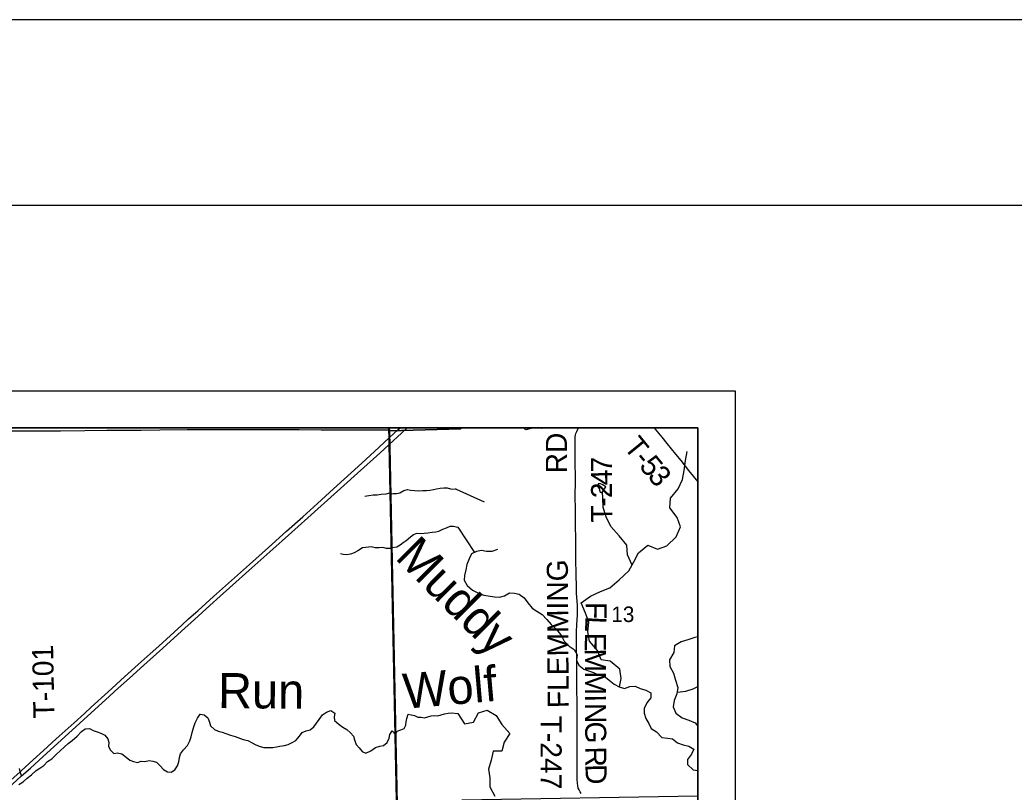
# Model space of a CAD drawing. Extents: x 0 to 34, y 0 to 22.
# Drawn here: x 7.072 to 9.752, y 19.918 to 22 of the extents above; entities that cross this region are included whole.
import ezdxf

# ---------------------------------------------------------------- set-up
doc = ezdxf.new("R2010")
doc.units = 0
for name, color, linetype in [('GM_X_County_Road', 7, 'Continuous'), ('GM_X_Interstate_Route', 7, 'Continuous'), ('GM_X_Major_River', 7, 'Continuous'), ('GM_X_Minor_Lake', 7, 'Continuous'), ('GM_X_Minor_River', 7, 'Continuous'), ('GM_X_Minor_River_Text', 7, 'Continuous'), ('GM_X_Section_Text', 7, 'Continuous'), ('GM_X_State_Shield', 7, 'Continuous'), ('GM_X_Township_Road', 7, 'Continuous'), ('GM_X_Township_Road_Text', 7, 'Continuous'), ('GM_X_US_Route', 7, 'Continuous'), ('SH_Border', 7, 'Continuous'), ('SH_Cut_Line', 7, 'Continuous'), ('SH_Data', 7, 'Continuous')]:
    doc.layers.add(name, color=color, linetype=linetype)

msp = doc.modelspace()

# ---------------------------------------------------------------- linework, layer by layer
at = {"layer": 'GM_X_County_Road'}
msp.add_lwpolyline([(7.0499, 20.8923), (7.0577, 20.8923), (7.0888, 20.8923), (7.1447, 20.8923), (7.182, 20.8924), (7.2473, 20.8928), (7.3063, 20.8935), (7.3684, 20.8939), (7.3995, 20.894), (7.4492, 20.8947), (7.5237, 20.8952), (7.5517, 20.8954), (7.5734, 20.8957), (7.62, 20.8958), (7.6604, 20.8959), (7.7132, 20.8958), (7.7443, 20.8958), (7.825, 20.8954), (7.884, 20.8951), (7.9337, 20.895), (7.9959, 20.8949), (8.0672, 20.8949)], dxfattribs=at)
at = {"layer": 'GM_X_Interstate_Route'}
for points in [[(8.1285, 16.8707), (8.1148, 17.8694), (8.0976, 18.2853), (8.0958, 18.3144), (8.0817, 18.88), (8.0959, 19.2713), (8.1023, 19.3817), (8.0929, 19.6339), (8.0678, 20.8562), (8.0675, 20.8733), (8.067, 20.8954), (8.0669, 20.9), (3.0331, 20.9), (3.0588, 19.9042), (3.067, 19.3838), (3.0747, 18.8969), (3.0724, 18.2926), (3.0939, 16.8719)], [(8.9, 16.8746), (8.9, 20.9), (8.0669, 20.9), (8.067, 20.8954), (8.0675, 20.8733), (8.0678, 20.8562), (8.0929, 19.6339), (8.1023, 19.3817), (8.0959, 19.2713), (8.0817, 18.88), (8.0958, 18.3144), (8.0976, 18.2853), (8.1148, 17.8694), (8.1285, 16.8707)]]:
    msp.add_lwpolyline(points, dxfattribs=at)
at = {"layer": 'GM_X_Major_River'}
for points in [[(8.4831, 20.9), (8.4784, 20.8982), (8.464, 20.8999), (8.4499, 20.8986), (8.4362, 20.895), (8.4319, 20.9)], [(8.3597, 20.572), (8.3447, 20.5664), (8.3303, 20.567), (8.317, 20.5691), (8.3029, 20.567), (8.2895, 20.5603), (8.2832, 20.5467), (8.2769, 20.5316), (8.274, 20.5168), (8.2708, 20.5024), (8.2702, 20.4891), (8.2784, 20.4749), (8.2927, 20.4626), (8.3085, 20.4547), (8.3225, 20.4492), (8.3514, 20.4443), (8.365, 20.4433), (8.3784, 20.4473), (8.3918, 20.4551), (8.4051, 20.4542), (8.4184, 20.4514), (8.4316, 20.4421), (8.4413, 20.4279), (8.4529, 20.4136), (8.4661, 20.4059), (8.48, 20.3969), (8.4931, 20.3834), (8.5043, 20.37), (8.5193, 20.3553), (8.5321, 20.3396), (8.5398, 20.325), (8.5526, 20.3115), (8.5661, 20.3026), (8.5743, 20.2884), (8.5726, 20.274), (8.5785, 20.2598), (8.592, 20.2498), (8.6052, 20.245), (8.6189, 20.2403), (8.6325, 20.2336), (8.6465, 20.2315), (8.6604, 20.2196), (8.674, 20.2091), (8.6875, 20.2017), (8.7023, 20.1977), (8.7165, 20.2028), (8.7309, 20.2034), (8.7445, 20.1975), (8.7597, 20.1931), (8.7729, 20.1857), (8.7731, 20.172), (8.7622, 20.1589), (8.7548, 20.1438), (8.7546, 20.1305), (8.7594, 20.1167), (8.7675, 20.1025), (8.7742, 20.0891), (8.7881, 20.0802), (8.8024, 20.0655), (8.8183, 20.0638), (8.8316, 20.0614), (8.8448, 20.0509), (8.8603, 20.045), (8.8754, 20.0414), (8.8886, 20.0336), (8.8827, 20.02), (8.8719, 20.0061), (8.8721, 19.9927), (8.8871, 19.9777), (8.9, 19.9758)]]:
    msp.add_lwpolyline(points, dxfattribs=at)
at = {"layer": 'GM_X_Minor_Lake'}
for points in [[(8.6517, 20.741), (8.6467, 20.7448), (8.6418, 20.7475), (8.6369, 20.7494), (8.6312, 20.749), (8.6304, 20.7414), (8.6334, 20.7361), (8.6346, 20.7319), (8.6368, 20.727), (8.6409, 20.7251)], [(8.0684, 20.7236), (8.0587, 20.7216), (8.0466, 20.7202), (8.0356, 20.7188), (8.0242, 20.7182), (8.0128, 20.7168), (8.0022, 20.715), (8.0022, 20.7146)], [(8.6409, 20.7251), (8.6517, 20.741)], [(8.0719, 20.5747), (8.0609, 20.5752), (8.051, 20.5772), (8.0412, 20.5765), (8.0298, 20.5766), (8.0189, 20.579), (8.0052, 20.5776), (7.9954, 20.5762), (7.9835, 20.5687), (7.9737, 20.5627), (7.9634, 20.5594), (7.9539, 20.5576), (7.9437, 20.5585), (7.9369, 20.5601)]]:
    msp.add_lwpolyline(points, dxfattribs=at)
at = {"layer": 'GM_X_Minor_River'}
for points in [[(8.6884, 20.2015), (8.6932, 20.2241), (8.6894, 20.2496), (8.6638, 20.2709), (8.6391, 20.2746), (8.6289, 20.2995), (8.6079, 20.3245), (8.6033, 20.35), (8.606, 20.3758), (8.5972, 20.4007), (8.5851, 20.4282), (8.6104, 20.4461), (8.6372, 20.4587), (8.6628, 20.4686), (8.6879, 20.4907), (8.7141, 20.5144), (8.7274, 20.5389), (8.7395, 20.5635), (8.7653, 20.5833), (8.791, 20.5734), (8.8159, 20.5818), (8.8409, 20.6062), (8.8527, 20.6331), (8.8436, 20.6587), (8.8242, 20.6848), (8.8261, 20.7103), (8.8466, 20.7355), (8.8587, 20.7608), (8.8625, 20.7855), (8.8663, 20.8116), (8.8709, 20.8367)], [(8.0715, 20.7216), (8.0786, 20.7232), (8.0873, 20.7228), (8.0964, 20.725), (8.1075, 20.7315), (8.117, 20.7334), (8.1254, 20.7318), (8.1356, 20.7314), (8.1478, 20.7299), (8.1585, 20.731), (8.168, 20.731), (8.1775, 20.7321), (8.187, 20.7336), (8.1957, 20.7355), (8.2056, 20.7378), (8.2148, 20.7381), (8.2239, 20.7385), (8.2326, 20.7358), (8.2479, 20.735), (8.2455, 20.735)], [(8.2479, 20.735), (8.324, 20.7003)], [(8.7226, 20.53), (8.7102, 20.5581), (8.7086, 20.5833), (8.6873, 20.6087), (8.6652, 20.6341), (8.6523, 20.6601), (8.6447, 20.6853), (8.6435, 20.7104), (8.6423, 20.7272)], [(8.0745, 20.5775), (8.0886, 20.5794), (8.097, 20.5844), (8.1053, 20.5908), (8.1137, 20.5965), (8.1248, 20.6064), (8.1332, 20.6128), (8.1431, 20.6158), (8.1522, 20.6151), (8.1625, 20.6158), (8.1716, 20.6169), (8.1838, 20.6188), (8.1933, 20.6199), (8.2016, 20.6214), (8.2123, 20.6267), (8.2226, 20.6305), (8.2321, 20.6347), (8.2409, 20.6354), (8.2523, 20.6327), (8.2512, 20.6328)], [(8.2525, 20.6323), (8.2974, 20.5643)], [(8.9, 20.3363), (8.8918, 20.3344), (8.8727, 20.3289), (8.8551, 20.3227), (8.8371, 20.3123), (8.8349, 20.2941), (8.8232, 20.2744), (8.8245, 20.2565), (8.8345, 20.2382), (8.8396, 20.2202), (8.8454, 20.2), (8.8432, 20.1829), (8.8361, 20.1651), (8.8328, 20.148), (8.8402, 20.1308), (8.8575, 20.1181), (8.8757, 20.1117), (8.8927, 20.1043), (8.9, 20.096)], [(8.8438, 20.1874), (8.8677, 20.1898), (8.8875, 20.1968), (8.9, 20.2024)], [(7.4308, 20.0012), (7.4406, 19.9988), (7.4507, 19.9892), (7.4594, 19.9789), (7.4703, 19.9723), (7.4805, 19.9715), (7.4904, 19.9778), (7.4973, 19.9888), (7.5004, 19.9994), (7.5028, 20.0111), (7.5052, 20.0209), (7.5132, 20.0315), (7.5239, 20.0439), (7.5301, 20.056), (7.5336, 20.0666), (7.5363, 20.0787), (7.5406, 20.0908), (7.5445, 20.1048), (7.5507, 20.1169), (7.5583, 20.1282), (7.5689, 20.1265), (7.5787, 20.1181), (7.5835, 20.1063), (7.5865, 20.0964), (7.5966, 20.0872), (7.6064, 20.0822), (7.6177, 20.0794), (7.6276, 20.0763), (7.64, 20.0716), (7.6529, 20.0677), (7.674, 20.0599), (7.6865, 20.0571), (7.6966, 20.0513), (7.7083, 20.0451), (7.7197, 20.0412), (7.7302, 20.0385), (7.7427, 20.0383), (7.7541, 20.0379), (7.764, 20.0397), (7.7734, 20.0422), (7.7856, 20.0436), (7.7958, 20.0466), (7.8065, 20.0521), (7.816, 20.0574), (7.8259, 20.0686), (7.8332, 20.0788), (7.8438, 20.0829), (7.8548, 20.0858), (7.8644, 20.0937), (7.8717, 20.1039), (7.8793, 20.1137), (7.8881, 20.1265), (7.8988, 20.1332), (7.9102, 20.1376), (7.9211, 20.1307), (7.9191, 20.1205), (7.9202, 20.1106), (7.9326, 20.1002), (7.9431, 20.0933), (7.9537, 20.0867), (7.9635, 20.0779), (7.9717, 20.0684), (7.9739, 20.0585), (7.9791, 20.0467), (7.987, 20.0371), (7.9952, 20.0272), (8.005, 20.0225), (8.0183, 20.0296), (8.0305, 20.0378), (8.0427, 20.0415), (8.0525, 20.0433), (8.0621, 20.0519), (8.0678, 20.0632), (8.0691, 20.0731), (8.0756, 20.0829), (8.0847, 20.0736)], [(8.0847, 20.0736), (8.0897, 20.0821), (8.0992, 20.0855), (8.1079, 20.0897), (8.1129, 20.0984), (8.1137, 20.1076), (8.1156, 20.1167), (8.1187, 20.1281), (8.1274, 20.1262), (8.1358, 20.1246), (8.1453, 20.1204), (8.1544, 20.1197), (8.1628, 20.1185), (8.1719, 20.1208), (8.1807, 20.1238), (8.1898, 20.1245), (8.1989, 20.1237), (8.2081, 20.126), (8.2168, 20.1287), (8.2263, 20.1309), (8.2355, 20.1317), (8.2532, 20.1298)], [(8.2532, 20.1298), (8.2707, 20.1016), (8.2952, 20.1069), (8.3081, 20.1319), (8.3321, 20.1391), (8.3563, 20.1244), (8.3711, 20.1006), (8.3929, 20.0763), (8.3773, 20.0522), (8.3716, 20.0287), (8.3477, 20.0279), (8.3424, 20.0044), (8.3356, 19.9801), (8.3387, 19.9565), (8.3394, 19.9318), (8.3528, 19.9073)], [(7.0697, 19.9387), (7.0808, 19.9454), (7.0918, 19.9552), (7.1037, 19.9642), (7.1159, 19.9758), (7.1262, 19.9821), (7.1365, 19.99), (7.1471, 20.0009), (7.1582, 20.008), (7.1704, 20.0197), (7.1815, 20.0302), (7.1914, 20.0388), (7.2025, 20.0493), (7.2131, 20.0572), (7.2265, 20.0692), (7.2383, 20.0812), (7.2482, 20.0887), (7.2596, 20.089), (7.2702, 20.0839), (7.2804, 20.0804), (7.2909, 20.0769), (7.3011, 20.0719), (7.309, 20.0619), (7.3123, 20.052), (7.3115, 20.0418), (7.3159, 20.0323), (7.3257, 20.0219), (7.3352, 20.0234), (7.3473, 20.0213), (7.3585, 20.0125), (7.3687, 20.0044), (7.3785, 20.0005), (7.3895, 19.9978), (7.399, 20.0011), (7.4088, 20.0002), (7.4206, 20.0028), (7.4308, 20.0012)]]:
    msp.add_lwpolyline(points, dxfattribs=at)
at = {"layer": 'GM_X_State_Shield'}
for points in [[(8.2605, 20.9), (8.0681, 20.9), (8.0683, 20.8917), (8.2605, 20.8973)], [(8.9, 19.9075), (8.9, 20.9), (8.2605, 20.9), (8.2605, 20.8973), (8.0683, 20.8917), (8.0896, 19.8843), (8.2647, 19.8857), (8.2647, 19.8969)]]:
    msp.add_lwpolyline(points, close=True, dxfattribs=at)
at = {"layer": 'GM_X_Township_Road'}
msp.add_line((7.0771, 19.9614), (7.0728, 19.9727), dxfattribs=at)
for points in [[(8.585, 19.9143), (8.5822, 19.9188), (8.5795, 19.9242), (8.5775, 19.9289), (8.5762, 19.9348), (8.5751, 19.9424), (8.5747, 19.9531), (8.5747, 19.9645), (8.5747, 19.9818), (8.5747, 20.0011), (8.5748, 20.0343), (8.5746, 20.1121), (8.5743, 20.1307), (8.574, 20.1649), (8.5739, 20.1897), (8.5734, 20.2611), (8.5734, 20.2828), (8.5729, 20.3045), (8.5726, 20.3218), (8.5726, 20.3493), (8.5738, 20.371), (8.5752, 20.3948), (8.5755, 20.4113), (8.5754, 20.4224), (8.5728, 20.453), (8.5725, 20.4757), (8.5721, 20.5003), (8.5712, 20.5509), (8.5707, 20.5725), (8.5706, 20.5987), (8.5703, 20.6388), (8.5701, 20.6542), (8.5698, 20.6749), (8.5695, 20.7215), (8.5696, 20.7511), (8.5691, 20.8227), (8.569, 20.8473), (8.5689, 20.8597), (8.569, 20.869), (8.5694, 20.8753), (8.5704, 20.8815), (8.5711, 20.8846), (8.5732, 20.8906), (8.5759, 20.8963), (8.5782, 20.9)], [(8.782, 20.9), (8.785, 20.8963), (8.8026, 20.8746), (8.8159, 20.858), (8.8396, 20.8289), (8.8536, 20.812), (8.8749, 20.7853), (8.9, 20.7545)], [(7.0728, 19.9727), (7.0716, 19.9815)]]:
    msp.add_lwpolyline(points, dxfattribs=at)
at = {"layer": 'GM_X_US_Route'}
for points in [[(8.0677, 20.8728), (8.0813, 20.8855), (8.0889, 20.8927), (8.0904, 20.8941), (8.097, 20.9)], [(8.068, 20.8556), (8.1007, 20.8853), (8.1165, 20.9)], [(7.0322, 19.9361), (7.0728, 19.9727), (7.076, 19.9757), (7.1084, 20.0048), (7.1359, 20.0299), (7.1704, 20.0613), (7.2188, 20.1051), (7.2464, 20.1302), (7.2648, 20.1469), (7.3107, 20.1887), (7.3545, 20.2284), (7.3914, 20.2617), (7.4237, 20.2908), (7.4467, 20.3117), (7.5087, 20.3683), (7.5271, 20.3849), (7.5526, 20.4077), (7.5943, 20.445), (7.6267, 20.4741), (7.6917, 20.5319), (7.7425, 20.5777), (7.7912, 20.6212), (7.8353, 20.6605), (7.8745, 20.6959), (7.9181, 20.7358), (7.9937, 20.805), (8.0282, 20.8364), (8.0677, 20.8728)], [(7.0407, 19.9284), (7.0771, 19.9614), (7.1006, 19.9827), (7.1351, 20.014), (7.2134, 20.0849), (7.2548, 20.1226), (7.3031, 20.1665), (7.3377, 20.1978), (7.3677, 20.2248), (7.4066, 20.2606), (7.4574, 20.3064), (7.5081, 20.3523), (7.5426, 20.3837), (7.5843, 20.421), (7.612, 20.4459), (7.6376, 20.4686), (7.6979, 20.5225), (7.7464, 20.5661), (7.8045, 20.6177), (7.8669, 20.6739), (7.9109, 20.7133), (7.9454, 20.7447), (7.9823, 20.778), (8.0422, 20.8322), (8.068, 20.8556)]]:
    msp.add_lwpolyline(points, dxfattribs=at)
at = {"layer": 'SH_Border'}
msp.add_lwpolyline([(1.5, 21.5), (33.5, 21.5), (33.5, 0.5), (1.5, 0.5)], close=True, dxfattribs=at)
at = {"layer": 'SH_Cut_Line'}
msp.add_lwpolyline([(0, 0), (34, 0), (34, 22), (0, 22)], close=True, dxfattribs=at)
for points in [[(8.1285, 16.8707), (8.1148, 17.8694), (8.0976, 18.2853), (8.0958, 18.3144), (8.0817, 18.88), (8.0959, 19.2713), (8.1023, 19.3817), (8.0929, 19.6339), (8.0678, 20.8562), (8.0675, 20.8733), (8.067, 20.8954), (8.0669, 20.9), (2.1, 20.9), (2.1, 14.1)], [(8.9, 14.1), (8.9, 20.9), (8.0669, 20.9), (8.067, 20.8954), (8.0675, 20.8733), (8.0678, 20.8562), (8.0929, 19.6339), (8.1023, 19.3817), (8.0959, 19.2713), (8.0817, 18.88), (8.0958, 18.3144), (8.0976, 18.2853), (8.1148, 17.8694), (8.1285, 16.8707)]]:
    msp.add_lwpolyline(points, dxfattribs=at)
at = {"layer": 'SH_Data'}
for p, q in [((2, 21), (9, 21)), ((9, 21), (9, 14)), ((2.1, 20.9), (8.9, 20.9)), ((8.9, 20.9), (8.9, 14.1))]:
    msp.add_line(p, q, dxfattribs=at)

# ---------------------------------------------------------------- texts
at = {"layer": 'GM_X_Minor_River_Text'}
for s, rotation, p in [('Muddy', 314.9903, (8.0807, 20.5484)), ('Wolf', 4.9915, (8.1092, 20.1424)), ('Run', 359.6383, (7.6062, 20.1444))]:
    msp.add_text(s, height=0.09473, rotation=rotation, dxfattribs=at).set_placement(p)
at = {"layer": 'GM_X_Section_Text'}
msp.add_text('13', height=0.04186, rotation=0, dxfattribs=at).set_placement((8.6664, 20.3765))
at = {"layer": 'GM_X_Township_Road_Text'}
for s, height, rotation, p in [('RD', 0.05682, 90, (8.5469, 20.7773)), ('T', 0.0568, 309.0801, (8.6977, 20.8476)), ('-', 0.0568, 309.1186, (8.7245, 20.8146)), ('5', 0.0568, 309.2789, (8.7394, 20.7964)), ('7', 0.0568, 90.3605, (8.6684, 20.7802)), ('3', 0.0568, 310.1685, (8.7621, 20.7685)), ('4', 0.0568, 90.322, (8.6686, 20.7454)), ('2', 0.0568, 90.2241, (8.6687, 20.7106)), ('T', 0.0568, 90.3156, (8.669, 20.6451)), ('-', 0.0568, 90.2223, (8.6688, 20.6875)), ('FLEMMING', 0.05682, 90.3787, (8.5519, 20.1445)), ('F', 0.0568, 269.5628, (8.5975, 20.4308)), ('L', 0.0568, 267.3591, (8.5972, 20.393)), ('E', 0.0568, 269.7666, (8.5952, 20.3479)), ('T-101', 0.05682, 91.1178, (7.1657, 20.1169)), ('M', 0.0568, 270.2506, (8.595, 20.3049)), ('M', 0.0568, 270.2708, (8.5953, 20.2432)), ('I', 0.0568, 270.2708, (8.5956, 20.1816)), ('N', 0.0568, 270.2731, (8.5957, 20.1582)), ('T-247', 0.05682, 270, (8.4757, 20.124)), ('G', 0.0568, 270.2714, (8.5959, 20.1082)), ('R', 0.0568, 270.279, (8.5962, 20.0407)), ('D', 0.0568, 271.495, (8.5965, 19.9927))]:
    msp.add_text(s, height=height, rotation=rotation, dxfattribs=at).set_placement(p)

doc.saveas('drawing.dxf')
